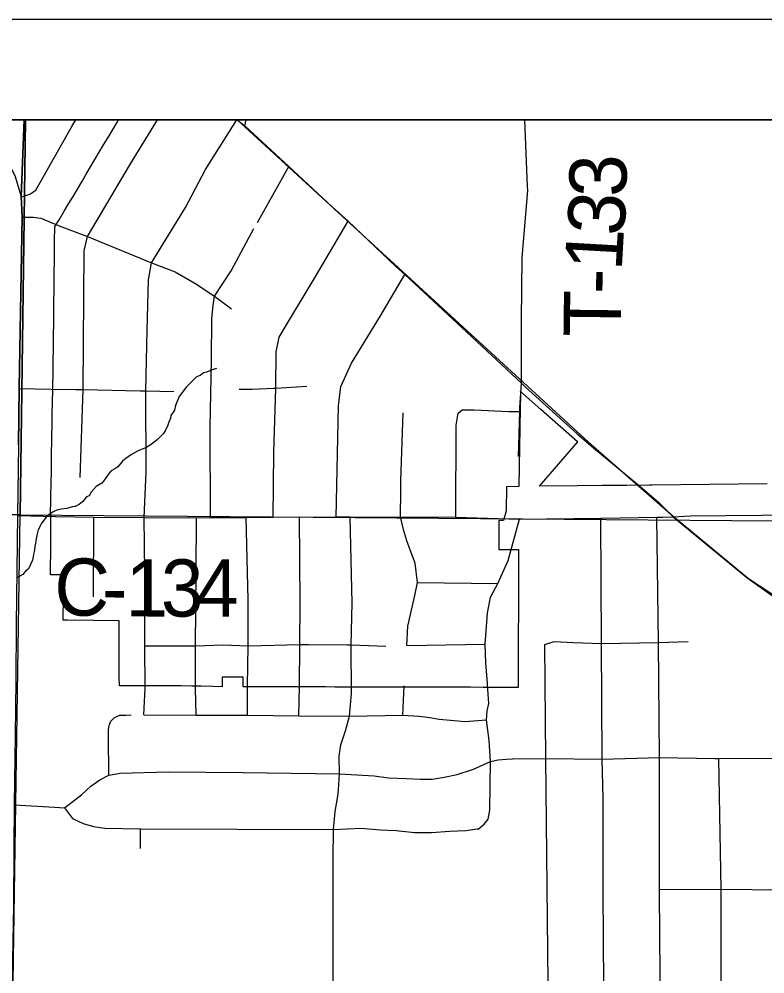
# Model space of a CAD drawing. Extents: x 0 to 34, y 0 to 22.
# Drawn here: x 3.043 to 3.784, y 20.051 to 21 of the extents above; entities that cross this region are included whole.
import ezdxf

# ---------------------------------------------------------------- set-up
doc = ezdxf.new("R2010")
doc.units = 0
for name, color, linetype in [('Default', 7, 'Continuous'), ('GM_X_City_Street', 7, 'Continuous'), ('GM_X_County_Road', 7, 'Continuous'), ('GM_X_County_Road_Text', 7, 'Continuous'), ('GM_X_Minor_River', 7, 'Continuous'), ('GM_X_Rail_Line', 7, 'Continuous'), ('GM_X_Section', 7, 'Continuous'), ('GM_X_State_Route', 7, 'Continuous'), ('GM_X_Township_Road', 7, 'Continuous'), ('GM_X_Township_Road_Text', 7, 'Continuous'), ('SH_Data', 7, 'Continuous')]:
    doc.layers.add(name, color=color, linetype=linetype)

msp = doc.modelspace()

# ---------------------------------------------------------------- linework, layer by layer
at = {"layer": 'Default'}
for points in [[(3.04909, 20.9), (2.1, 20.9), (2.1, 20.51749), (3.04368, 20.50725)], [(4.04968, 20.9), (3.04909, 20.9), (3.04368, 20.50725), (4.04262, 20.49916)], [(2.1, 20.51749), (2.1, 19.52883), (3.02863, 19.51298), (3.04368, 20.50725)]]:
    msp.add_lwpolyline(points, close=True, dxfattribs=at)
at = {"layer": 'GM_X_City_Street'}
for p, q in [((3.04298, 20.63292), (3.07441, 20.63226)), ((3.16678, 20.30859), (3.16808, 20.33493)), ((3.21874, 20.30812), (3.21796, 20.3349)), ((3.26963, 20.30831), (3.26987, 20.33727)), ((3.32075, 20.30764), (3.32149, 20.33654)), ((3.42418, 20.30812), (3.42539, 20.33723)), ((3.0381, 20.21901), (3.07783, 20.21658)), ((3.16344, 20.17564), (3.16344, 20.19523))]:
    msp.add_line(p, q, dxfattribs=at)
for points in [[(3.045, 20.82328), (3.0534, 20.82593), (3.05925, 20.83002), (3.09494, 20.8932), (3.09918, 20.9)], [(3.04579, 20.80329), (3.05676, 20.80329), (3.06421, 20.80212), (3.08263, 20.79467)], [(3.62395, 20.03926), (3.6233, 20.13275), (3.6233, 20.2256), (3.62243, 20.26435), (3.62155, 20.37931), (3.62096, 20.5039)], [(3.69482, 19.56857), (3.68199, 19.60366), (3.67346, 19.63986), (3.66862, 19.67335), (3.66721, 19.70291), (3.66853, 19.72515), (3.67144, 19.75641), (3.67707, 19.78738), (3.68411, 19.82117), (3.68772, 19.84541), (3.69081, 19.87751), (3.6889, 19.90242), (3.68698, 19.93979), (3.68219, 19.97621), (3.68014, 20.00905), (3.67932, 20.13142), (3.67932, 20.13495), (3.67923, 20.26606), (3.67815, 20.38022), (3.67661, 20.50504)], [(3.49817, 20.19523), (3.49894, 20.1947), (3.50505, 20.1997), (3.50894, 20.2047), (3.51061, 20.21359), (3.51135, 20.26217), (3.51005, 20.28302), (3.50728, 20.30357), (3.50783, 20.31247), (3.5095, 20.31969), (3.50894, 20.32912), (3.50783, 20.34412), (3.50672, 20.35968), (3.50598, 20.37885)], [(3.55769, 19.11108), (3.55853, 19.2406), (3.55746, 19.38351), (3.55615, 19.50881), (3.55615, 19.5161), (3.55871, 19.52292), (3.56227, 19.5317), (3.56684, 19.54117), (3.56701, 19.56468), (3.56681, 19.62214), (3.5676, 19.72561), (3.56681, 19.83066), (3.5689, 20.0099), (3.5662, 20.26492), (3.56539, 20.37839)], [(3.56539, 20.37839), (3.57475, 20.38136), (3.5937, 20.38022), (3.62155, 20.37931), (3.67815, 20.38022), (3.70782, 20.38126)], [(3.35499, 20.00563), (3.35472, 20.10395), (3.35472, 20.16585), (3.35513, 20.19464), (3.35681, 20.21246), (3.35959, 20.22776), (3.36029, 20.23402), (3.36104, 20.24981), (3.36098, 20.2674), (3.36237, 20.27853), (3.36724, 20.29244), (3.37127, 20.30717), (3.37314, 20.32964)], [(3.13201, 20.24851), (3.13137, 20.28746), (3.13137, 20.29389), (3.13214, 20.29801), (3.13368, 20.30212), (3.13754, 20.30598), (3.14269, 20.30804), (3.1486, 20.3083), (3.15401, 20.30855)], [(3.16678, 20.30859), (3.21874, 20.30812), (3.26963, 20.30831), (3.32075, 20.30764), (3.37127, 20.30717), (3.42418, 20.30812), (3.44039, 20.30717), (3.45088, 20.30574), (3.46041, 20.30431), (3.47518, 20.30288), (3.48567, 20.30192), (3.50728, 20.30357)], [(3.07783, 20.21658), (3.08777, 20.21598), (3.10468, 20.22899), (3.11379, 20.23745), (3.1229, 20.24395), (3.13201, 20.24851), (3.14307, 20.25046), (3.19122, 20.25176), (3.2654, 20.25111), (3.36104, 20.24981), (3.39553, 20.24786), (3.40985, 20.2459), (3.42741, 20.24526), (3.44173, 20.24461), (3.45344, 20.24461), (3.46515, 20.24656), (3.47817, 20.24916), (3.49443, 20.25437), (3.51135, 20.26217), (3.51877, 20.26364), (3.527, 20.26435), (3.53325, 20.26463), (3.5662, 20.26492), (3.62243, 20.26435), (3.67923, 20.26606), (3.73423, 20.265)], [(3.73395, 19.01316), (3.73321, 19.11009), (3.73259, 19.26108), (3.73239, 19.37081), (3.73172, 19.50718), (3.73392, 19.53591), (3.73694, 19.55557), (3.73934, 19.57345), (3.74062, 19.59399), (3.74073, 19.59565), (3.73846, 19.61683), (3.73316, 19.64179), (3.72787, 19.66599), (3.72635, 19.68868), (3.72635, 19.70683), (3.7284, 19.73083), (3.74306, 19.84049), (3.74536, 19.89412), (3.74109, 19.97336), (3.74046, 20.05386), (3.74046, 20.13521), (3.73831, 20.26492)], [(3.73423, 20.265), (3.73831, 20.26492), (3.79474, 20.26543)], [(3.08777, 20.21598), (3.09577, 20.20532), (3.10646, 20.20057), (3.11655, 20.1976), (3.12782, 20.19582), (3.16344, 20.19523), (3.35513, 20.19464), (3.38244, 20.19582), (3.40202, 20.19404), (3.41746, 20.19345), (3.43585, 20.19167), (3.45247, 20.19167), (3.47087, 20.19285), (3.4869, 20.19345), (3.49817, 20.19523)], [(3.67932, 20.13495), (3.74046, 20.13521), (3.80179, 20.13463), (3.86522, 20.1349), (3.88478, 20.13495)]]:
    msp.add_lwpolyline(points, dxfattribs=at)
at = {"layer": 'GM_X_County_Road'}
for p, q in [((3.61362, 20.57398), (3.65767, 20.53744)), ((3.04141, 20.50658), (3.07915, 20.50573)), ((3.35775, 20.50489), (3.37172, 20.50489)), ((3.51903, 20.50368), (3.54007, 20.50308)), ((3.68276, 20.50509), (3.69302, 20.50518))]:
    msp.add_line(p, q, dxfattribs=at)
for points in [[(3.04141, 20.50658), (3.04227, 20.57618), (3.04298, 20.63292), (3.04579, 20.80329), (3.045, 20.82328), (3.03878, 20.84406), (3.03167, 20.85738), (3.02152, 20.87361), (3.00796, 20.89273), (3.00343, 20.9)], [(3.25957, 20.9), (3.26697, 20.89379), (3.31086, 20.85365), (3.35382, 20.81356), (3.36985, 20.79914), (3.4172, 20.75425), (3.4262, 20.74624), (3.48316, 20.69309), (3.54205, 20.63819), (3.54605, 20.63403), (3.59746, 20.58791), (3.61362, 20.57398)], [(3.65767, 20.53744), (3.66208, 20.53379), (3.67873, 20.51948), (3.69302, 20.50518), (3.76605, 20.44485), (3.82139, 20.40555), (3.82958, 20.40015), (3.88735, 20.36326), (3.89611, 20.35733), (3.94814, 20.32515), (3.97181, 20.31036), (3.97785, 20.30666), (4.04037, 20.26671), (4.06059, 20.25376), (4.11731, 20.21837), (4.18891, 20.17355), (4.24098, 20.14131), (4.27659, 20.11783)], [(3.07915, 20.50573), (3.11689, 20.50489), (3.16693, 20.50452), (3.21915, 20.50439), (3.23297, 20.50472), (3.2685, 20.50451), (3.29511, 20.50489), (3.32141, 20.50538), (3.35775, 20.50489)], [(3.37172, 20.50489), (3.42191, 20.50535), (3.47694, 20.50489), (3.51903, 20.50368)], [(3.54007, 20.50308), (3.62096, 20.5039), (3.62197, 20.50392)], [(3.62197, 20.50392), (3.67661, 20.50504), (3.68276, 20.50509)], [(3.69302, 20.50518), (3.7099, 20.5062), (3.85171, 20.50753), (3.86497, 20.50767)]]:
    msp.add_lwpolyline(points, dxfattribs=at)
at = {"layer": 'GM_X_Minor_River'}
msp.add_lwpolyline([(3.23888, 20.65284), (3.23544, 20.65176), (3.23276, 20.65067), (3.22894, 20.64922), (3.22589, 20.64851), (3.22281, 20.64591), (3.21898, 20.64445), (3.21357, 20.63922), (3.20893, 20.63436), (3.20659, 20.63136), (3.20425, 20.62798), (3.20192, 20.62498), (3.19796, 20.61593), (3.19711, 20.61138), (3.1936, 20.60612), (3.19317, 20.60346), (3.19157, 20.59931), (3.19038, 20.59629), (3.188, 20.59063), (3.18605, 20.588), (3.18334, 20.58501), (3.17986, 20.58165), (3.17409, 20.57719), (3.16871, 20.57386), (3.16412, 20.57204), (3.1603, 20.57059), (3.15454, 20.56727), (3.14877, 20.56319), (3.14531, 20.56059), (3.14065, 20.55497), (3.13796, 20.55311), (3.13412, 20.5509), (3.1318, 20.54828), (3.1275, 20.54189), (3.12479, 20.5389), (3.11941, 20.53557), (3.11437, 20.52996), (3.11241, 20.52619), (3.10973, 20.5251), (3.10585, 20.52061), (3.10238, 20.51763), (3.09854, 20.51541), (3.0955, 20.51509), (3.09016, 20.51366), (3.08445, 20.513), (3.08026, 20.51194), (3.07643, 20.5101), (3.0722, 20.50714), (3.0695, 20.50491), (3.06522, 20.49928), (3.06168, 20.4925), (3.06046, 20.48834), (3.05961, 20.48341), (3.05918, 20.48075), (3.05833, 20.47583), (3.05789, 20.47203), (3.05706, 20.46825), (3.05663, 20.46559), (3.0558, 20.46218), (3.05383, 20.45804), (3.05185, 20.45351), (3.04915, 20.45128), (3.04643, 20.4479), (3.04106, 20.44496)], dxfattribs=at)
at = {"layer": 'GM_X_Rail_Line'}
msp.add_lwpolyline([(3.25957, 20.9), (3.60823, 20.57966), (3.6929, 20.50592), (3.76774, 20.44387), (4.03449, 20.26899), (4.19117, 20.26046), (4.48816, 20.25779), (4.61357, 20.23074), (4.6473, 20.21621), (4.81604, 20.13517), (4.93992, 20.07043), (5.01672, 20.06971), (5.34106, 20.06734)], dxfattribs=at)
at = {"layer": 'GM_X_Section'}
msp.add_lwpolyline([(3.04368, 20.50725), (4.04262, 20.49916), (4.05087, 19.50181), (3.02863, 19.51298)], close=True, dxfattribs=at)
at = {"layer": 'GM_X_State_Route'}
msp.add_lwpolyline([(3.78626, 20.53807), (3.67165, 20.53682), (3.66946, 20.5368), (3.64686, 20.53655), (3.62279, 20.53629), (3.59755, 20.53602), (3.56015, 20.53561), (3.59798, 20.57977), (3.59792, 20.57983), (3.56141, 20.61211), (3.54121, 20.62998), (3.54115, 20.63003), (3.54107, 20.62541), (3.54087, 20.61356), (3.53954, 20.53539), (3.52705, 20.53525), (3.52692, 20.51114), (3.52436, 20.50167), (3.51943, 20.50167), (3.51942, 20.47285), (3.52425, 20.47286), (3.52856, 20.47287), (3.53907, 20.47288), (3.53903, 20.44432), (3.53902, 20.43295), (3.539, 20.41874), (3.53899, 20.41401), (3.53898, 20.40435), (3.53896, 20.39488), (3.53894, 20.38068), (3.53894, 20.37935), (3.53891, 20.36647), (3.5389, 20.36171), (3.53889, 20.35701), (3.53888, 20.35411), (3.53887, 20.34754), (3.53887, 20.34653), (3.53885, 20.33896), (3.53884, 20.33572), (3.52565, 20.33575), (3.51372, 20.33577), (3.50411, 20.33579), (3.49142, 20.33582), (3.48195, 20.33584), (3.47096, 20.33586), (3.46869, 20.33587), (3.46149, 20.33588), (3.45069, 20.3359), (3.44854, 20.33591), (3.44122, 20.33592), (3.4302, 20.33589), (3.42072, 20.33591), (3.40808, 20.33599), (3.39861, 20.33601), (3.39826, 20.33601), (3.38914, 20.33603), (3.37741, 20.33606), (3.36794, 20.33603), (3.35659, 20.33612), (3.34712, 20.33615), (3.33737, 20.33618), (3.32602, 20.33621), (3.31655, 20.33624), (3.30519, 20.33627), (3.29572, 20.3363), (3.2861, 20.33632), (3.27489, 20.33636), (3.26542, 20.33638), (3.26543, 20.3458), (3.2446, 20.34589), (3.24459, 20.33642), (3.23515, 20.3366), (3.22378, 20.33681), (3.21431, 20.33699), (3.20385, 20.33718), (3.19438, 20.33722), (3.19344, 20.33722), (3.18491, 20.33726), (3.1726, 20.33731), (3.16313, 20.33735), (3.15082, 20.3374), (3.1423, 20.33743), (3.14226, 20.34614), (3.14222, 20.35561), (3.14218, 20.36508), (3.14213, 20.37455), (3.14209, 20.38402), (3.14205, 20.39349), (3.14201, 20.402), (3.11645, 20.40233), (3.09088, 20.40266), (3.08658, 20.40271), (3.08681, 20.42573), (3.08684, 20.42895), (3.08692, 20.43709), (3.08702, 20.44751), (3.07387, 20.44773), (3.07394, 20.4572), (3.07403, 20.46865), (3.07409, 20.47717), (3.07427, 20.49989), (3.0743, 20.50318), (3.07433, 20.507), (3.07388, 20.51084), (3.07404, 20.5193), (3.0742, 20.52781), (3.07436, 20.53632), (3.07468, 20.55334), (3.07483, 20.56185), (3.07499, 20.57036), (3.07515, 20.57887), (3.07531, 20.58738), (3.07546, 20.59589), (3.07562, 20.6044), (3.07594, 20.62142), (3.0761, 20.62999), (3.07624, 20.63757), (3.07635, 20.64582), (3.07647, 20.65412), (3.07658, 20.66243), (3.0767, 20.67073), (3.07682, 20.67904), (3.07687, 20.68317), (3.07692, 20.68734), (3.07701, 20.69565), (3.0771, 20.70396), (3.07719, 20.71226), (3.07728, 20.72057), (3.07737, 20.72887), (3.07746, 20.73718), (3.07755, 20.74549), (3.07773, 20.7621), (3.07782, 20.7704), (3.07791, 20.77871), (3.07807, 20.79397), (3.08235, 20.80041), (3.08237, 20.80043), (3.08755, 20.80915), (3.09191, 20.81646), (3.09626, 20.82378), (3.10061, 20.8311), (3.10496, 20.83841), (3.10931, 20.84573), (3.11366, 20.85304), (3.11801, 20.86036), (3.12235, 20.86768), (3.1267, 20.87499), (3.13106, 20.88231), (3.13541, 20.88962), (3.13976, 20.89694), (3.14158, 20.9), (2.23692, 20.9)], dxfattribs=at)
at = {"layer": 'GM_X_Township_Road'}
for p, q in [((3.26697, 20.89379), (3.26829, 20.9)), ((3.54818, 20.8335), (3.54536, 20.9)), ((3.27981, 20.79796), (3.31086, 20.85365)), ((3.5406, 20.61366), (3.54205, 20.63819)), ((3.16859, 20.63051), (3.19662, 20.62999)), ((3.11653, 20.42588), (3.11689, 20.50489)), ((3.37172, 20.50489), (3.35775, 20.50489)), ((3.4388, 20.44001), (3.51848, 20.43896)), ((3.1676, 20.37719), (3.21592, 20.37719)), ((3.33032, 20.37829), (3.36895, 20.37794)), ((3.42798, 20.37747), (3.50598, 20.37885))]:
    msp.add_line(p, q, dxfattribs=at)
for points in [[(3.04204, 20.57671), (3.04275, 20.63346), (3.04555, 20.80382), (3.04477, 20.82381), (3.04782, 20.9), (2.1, 20.9)], [(7.58449, 20.9), (3.04782, 20.9), (3.04477, 20.82381), (3.04555, 20.80382), (3.04275, 20.63346), (3.04204, 20.57671), (3.04118, 20.50711), (3.04032, 20.45205), (3.04002, 20.42519), (3.03971, 20.39834), (3.03926, 20.34251), (3.03868, 20.28829), (3.03787, 20.21954), (3.03751, 20.17509), (3.03707, 20.11919), (3.03623, 20.06466), (3.03534, 20.00735), (3.03321, 19.85331), (3.0316, 19.80203), (3.02935, 19.71288), (3.02896, 19.63669), (3.02646, 19.50599), (3.02646, 19.40492), (3.02912, 19.22937)], [(3.10335, 20.54451), (3.10624, 20.632), (3.10731, 20.76958), (3.11049, 20.78382), (3.15341, 20.85605), (3.18015, 20.9)], [(3.16693, 20.50452), (3.16887, 20.55007), (3.16859, 20.63051), (3.17009, 20.69082), (3.17136, 20.74094), (3.17435, 20.75782), (3.20821, 20.81271), (3.22792, 20.85039), (3.25896, 20.9)], [(3.54205, 20.63819), (3.5421, 20.70111), (3.54284, 20.76288), (3.54834, 20.8296), (3.54818, 20.8335)], [(3.08263, 20.79467), (3.11049, 20.78382), (3.17435, 20.75782), (3.19787, 20.74881), (3.21904, 20.73666), (3.23041, 20.72881), (3.23674, 20.72448), (3.25393, 20.71196)], [(3.29511, 20.50489), (3.29591, 20.56914), (3.29783, 20.6333), (3.29837, 20.66935), (3.3011, 20.68382), (3.30848, 20.69611), (3.33687, 20.74335), (3.36985, 20.79914)], [(3.23297, 20.50472), (3.2327, 20.59398), (3.23407, 20.66129), (3.23433, 20.70256), (3.2357, 20.71549), (3.23674, 20.72448), (3.25334, 20.74979), (3.27598, 20.79195)], [(3.35775, 20.50489), (3.36005, 20.61565), (3.36262, 20.63488), (3.37319, 20.65795), (3.40178, 20.70505), (3.4262, 20.74624)], [(3.07441, 20.63226), (3.09886, 20.63181), (3.10624, 20.632), (3.16292, 20.63062), (3.16859, 20.63051)], [(3.26151, 20.63221), (3.27434, 20.63221), (3.29559, 20.6332)], [(3.29559, 20.6332), (3.29783, 20.6333), (3.32868, 20.63522)], [(3.53908, 20.56522), (3.54038, 20.60998), (3.5406, 20.61366)], [(3.42207, 20.53134), (3.42214, 20.54108), (3.42454, 20.60859)], [(3.47694, 20.50489), (3.47719, 20.59626), (3.47911, 20.60844)], [(3.47911, 20.60844), (3.48312, 20.61149), (3.49514, 20.61149), (3.52965, 20.61011), (3.54038, 20.60998)], [(3.43603, 20.4272), (3.4388, 20.44001), (3.43627, 20.45936), (3.43176, 20.47151), (3.42808, 20.48134), (3.42506, 20.49149), (3.42191, 20.50535), (3.42207, 20.53134)], [(3.16808, 20.33493), (3.1676, 20.37719), (3.16777, 20.44993), (3.16693, 20.50452)], [(3.21796, 20.3349), (3.21786, 20.37719), (3.21866, 20.45097), (3.21915, 20.50439)], [(3.26987, 20.33727), (3.27044, 20.37719), (3.27035, 20.42274), (3.2685, 20.50451)], [(3.32149, 20.33654), (3.32163, 20.37837), (3.32207, 20.41933), (3.32141, 20.50538)], [(3.37314, 20.32964), (3.37281, 20.3779), (3.3739, 20.41933), (3.37172, 20.50489)], [(3.50598, 20.37885), (3.50846, 20.40961), (3.5112, 20.42527), (3.51848, 20.43896), (3.52878, 20.4618), (3.54007, 20.50308)], [(3.42798, 20.37747), (3.42908, 20.3967), (3.43347, 20.41538), (3.43603, 20.4272)], [(3.21592, 20.37719), (3.21786, 20.37719), (3.24556, 20.37814), (3.27044, 20.37719), (3.32163, 20.37837), (3.33032, 20.37829)], [(3.36895, 20.37794), (3.37281, 20.3779), (3.40732, 20.37673)]]:
    msp.add_lwpolyline(points, dxfattribs=at)
at = {"layer": 'SH_Data'}
for p, q in [((2, 21), (9, 21)), ((2.1, 20.9), (8.9, 20.9))]:
    msp.add_line(p, q, dxfattribs=at)

# ---------------------------------------------------------------- texts
at = {"layer": 'GM_X_County_Road_Text'}
for s, rotation, p in [('C', 358.31371, (3.07685, 20.40789)), ('1', 359.80591, (3.14845, 20.40629)), ('3', 359.96125, (3.18361, 20.40617)), ('4', 0.00101, (3.21866, 20.40615)), ('-', 359.50125, (3.12478, 20.4065))]:
    msp.add_text(s, height=0.05682, rotation=rotation, dxfattribs=at).set_placement(p)
at = {"layer": 'GM_X_Township_Road_Text'}
for s, rotation, p in [('3', 89.90331, (3.64659, 20.82327)), ('3', 85.47317, (3.64364, 20.78359)), ('1', 86.77196, (3.64169, 20.74899)), ('-', 88.61042, (3.64114, 20.72614)), ('T', 89.31426, (3.64064, 20.68383))]:
    msp.add_text(s, height=0.05682, rotation=rotation, dxfattribs=at).set_placement(p)

doc.saveas('drawing.dxf')
